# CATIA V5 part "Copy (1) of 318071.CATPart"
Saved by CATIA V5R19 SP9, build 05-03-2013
Part number: Copy (1) of 318071
Source: Unknown
Bounding box of the stored display mesh (mm): x -136 to 26.779, y 110.238 to 128.64, z 475.082 to 497.334
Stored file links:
  D:\16-SIL\kale oto\R19_V1\Copy (1) of 318071.CATPart
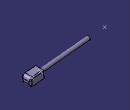
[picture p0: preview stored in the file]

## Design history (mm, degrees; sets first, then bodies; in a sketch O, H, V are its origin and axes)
Set1
  Point1: stored without definition
  Point2 "Point.3": stored without definition
  Point3 "Point.4": stored without definition
Body1 "241\\236\\235\\MANIFOLD_SOLID_BREP #159996" (main body)
  Solid1: solid without history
